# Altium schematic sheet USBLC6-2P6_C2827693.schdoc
size 127 x 101 mm
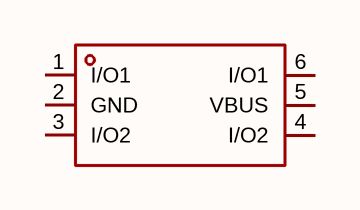
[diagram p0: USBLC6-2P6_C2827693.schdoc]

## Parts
D?  usblc6-2p6_c2827693  [SOT-666-6_L1.6-W1.2-P0.50-LS1.6-BL]  (value not drawn)

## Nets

Not connected (* = marked no-connect by the designer): D? 1(I/O1) 2(GND) 3(I/O2) 4(I/O2) 5(VBUS) 6(I/O1)

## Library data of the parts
D? = usblc6-2p6_c2827693: 极性:单向;反向截止电压(Vrwm):5V;最大钳位电压:14V;峰值脉冲电流(Ipp):5.5A;峰值脉冲功率(Ppp):80W;击穿电压:6V;; Manufacturer: TECH PUBLIC(台舟); AddInBom: yes; ModelId: f8913a8ea8464b42b2a2a677f05bfd83; ModelName: SOT-666-6P_L1.6-W1.2-H0.6-LS1.6-P0.50; ModelTransform: 62.992,62.992,0,90,0,0,-0.005,0,0; polarity: 单向; Reverse Stand-Off Voltage (Vrwm): 5V; Maximum Clamping Voltage: 14V; Peak Pulse Current (Ipp): 5.5A; Peak Pulse Power Dissipation (Ppp): 80W; Breakdown Voltage: 6V; Reverse Leakage Current (Ir): 80nA; Number of Lines: 双路; level of protection: IEC 61000-4-2; Type: ESD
